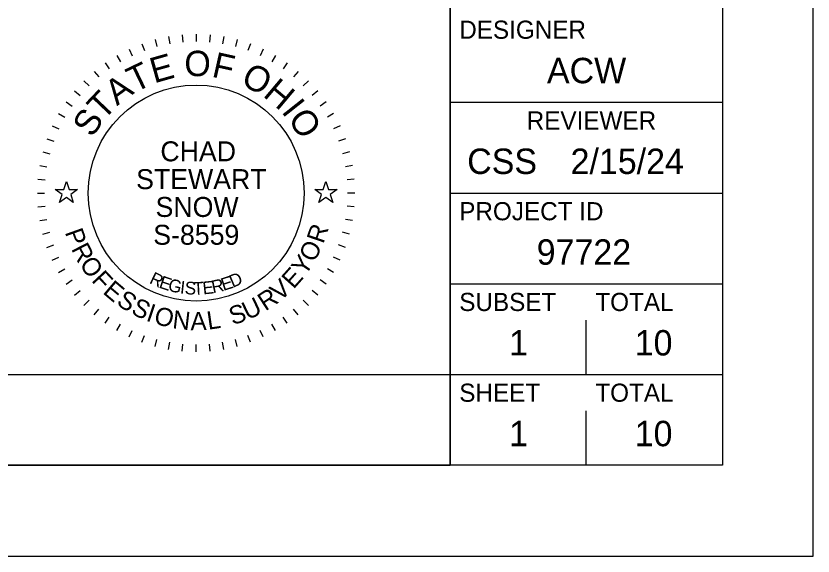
# Model space of a CAD drawing. Extents: x 0 to 59.1, y -2.4 to 22.
# Drawn here: x 29.607 to 34, y 0 to 2.976 of the extents above; entities that cross this region are included whole.
import ezdxf

# ---------------------------------------------------------------- set-up
doc = ezdxf.new("R2010")
doc.units = 0
for name, color, linetype in [('Default', 7, 'Continuous'), ('SH_Border', 7, 'Continuous'), ('SH_Cut_Line', 7, 'Continuous'), ('SH_Data', 7, 'Continuous')]:
    doc.layers.add(name, color=color, linetype=linetype)

msp = doc.modelspace()

# ---------------------------------------------------------------- linework, layer by layer
at = {"layer": 'Default'}
for points in [[(29.8236, 2.02), (29.8705, 2.02), (29.885, 2.0645), (29.8995, 2.02), (29.9464, 2.02), (29.9085, 1.9924), (29.923, 1.9478), (29.885, 1.9754), (29.847, 1.9478), (29.8615, 1.9924)], [(31.2536, 2.02), (31.3005, 2.02), (31.315, 2.0645), (31.3295, 2.02), (31.3764, 2.02), (31.3385, 1.9924), (31.353, 1.9478), (31.315, 1.9754), (31.277, 1.9478), (31.2915, 1.9924)]]:
    msp.add_lwpolyline(points, close=True, dxfattribs=at)
at = {"layer": 'SH_Border'}
for p, q in [((32, 0.5), (32, 21.5)), ((32, 2.5), (33.5, 2.5)), ((32, 2), (33.5, 2)), ((32, 1.5), (33.5, 1.5)), ((32, 1), (33.5, 1))]:
    msp.add_line(p, q, dxfattribs=at)
msp.add_lwpolyline([(1.5, 21.5), (33.5, 21.5), (33.5, 0.5), (1.5, 0.5)], close=True, dxfattribs=at)
at = {"layer": 'SH_Cut_Line'}
msp.add_lwpolyline([(0, 0), (34, 0), (34, 22), (0, 22)], close=True, dxfattribs=at)
at = {"layer": 'SH_Data'}
for p, q in [((32, 3.75), (32, 0.5)), ((30.4481, 2.8617), (30.455, 2.8223)), ((30.5237, 2.8717), (30.5272, 2.8318)), ((30.6, 2.875), (30.6, 2.835)), ((30.6763, 2.8717), (30.6728, 2.8318)), ((30.7519, 2.8617), (30.745, 2.8223)), ((30.3007, 2.8222), (30.3144, 2.7846)), ((30.3735, 2.8452), (30.3839, 2.8065)), ((30.8265, 2.8452), (30.8161, 2.8065)), ((30.8993, 2.8222), (30.8856, 2.7846)), ((30.2302, 2.793), (30.2471, 2.7568)), ((30.9698, 2.793), (30.9529, 2.7568)), ((30.1625, 2.7578), (30.1825, 2.7231)), ((31.0375, 2.7578), (31.0175, 2.7231)), ((30.0981, 2.7168), (30.1211, 2.684)), ((31.1019, 2.7168), (31.0789, 2.684)), ((30.0376, 2.6703), (30.0633, 2.6396)), ((31.1624, 2.6703), (31.1367, 2.6396)), ((29.9813, 2.6187), (30.0096, 2.5904)), ((31.2187, 2.6187), (31.1904, 2.5904)), ((29.9297, 2.5624), (29.9604, 2.5367)), ((31.2703, 2.5624), (31.2396, 2.5367)), ((29.8832, 2.5019), (29.916, 2.4789)), ((31.3168, 2.5019), (31.284, 2.4789)), ((29.8422, 2.4375), (29.8769, 2.4175)), ((31.3578, 2.4375), (31.3231, 2.4175)), ((29.807, 2.3698), (29.8432, 2.3529)), ((31.393, 2.3698), (31.3568, 2.3529)), ((29.7778, 2.2993), (29.8154, 2.2856)), ((31.4222, 2.2993), (31.3846, 2.2856)), ((29.7548, 2.2265), (29.7935, 2.2161)), ((31.4452, 2.2265), (31.4065, 2.2161)), ((29.7383, 2.1519), (29.7777, 2.145)), ((31.4617, 2.1519), (31.4223, 2.145)), ((29.7283, 2.0763), (29.7682, 2.0728)), ((31.4717, 2.0763), (31.4318, 2.0728)), ((29.725, 2), (29.765, 2)), ((31.475, 2), (31.435, 2)), ((29.7283, 1.9237), (29.7682, 1.9272)), ((31.4717, 1.9237), (31.4318, 1.9272)), ((29.7383, 1.8481), (29.7777, 1.855)), ((31.4617, 1.8481), (31.4223, 1.855)), ((29.7548, 1.7735), (29.7935, 1.7839)), ((31.4452, 1.7735), (31.4065, 1.7839)), ((29.7778, 1.7007), (29.8154, 1.7144)), ((31.4222, 1.7007), (31.3846, 1.7144)), ((29.807, 1.6302), (29.8432, 1.6471)), ((31.393, 1.6302), (31.3568, 1.6471)), ((29.8422, 1.5625), (29.8769, 1.5825)), ((31.3578, 1.5625), (31.3231, 1.5825)), ((29.8832, 1.4981), (29.916, 1.5211)), ((31.3168, 1.4981), (31.284, 1.5211)), ((29.9297, 1.4376), (29.9604, 1.4633)), ((31.2703, 1.4376), (31.2396, 1.4633)), ((29.9813, 1.3813), (30.0096, 1.4096)), ((31.2187, 1.3813), (31.1904, 1.4096)), ((30.0376, 1.3297), (30.0633, 1.3604)), ((31.1624, 1.3297), (31.1367, 1.3604)), ((30.0981, 1.2832), (30.1211, 1.316)), ((30.1625, 1.2422), (30.1825, 1.2769)), ((31.0375, 1.2422), (31.0175, 1.2769)), ((31.1019, 1.2832), (31.0789, 1.316)), ((32.75, 1), (32.75, 1.3)), ((30.2302, 1.207), (30.2471, 1.2432)), ((30.9698, 1.207), (30.9529, 1.2432)), ((30.3007, 1.1778), (30.3144, 1.2154)), ((30.3735, 1.1548), (30.3839, 1.1935)), ((30.8265, 1.1548), (30.8161, 1.1935)), ((30.8993, 1.1778), (30.8856, 1.2154)), ((30.4481, 1.1383), (30.455, 1.1777)), ((30.5237, 1.1283), (30.5272, 1.1682)), ((30.6, 1.125), (30.6, 1.165)), ((30.6763, 1.1283), (30.6728, 1.1682)), ((30.7519, 1.1383), (30.745, 1.1777)), ((32.75, 0.5), (32.75, 0.8)), ((29.2, 0.5), (32, 0.5))]:
    msp.add_line(p, q, dxfattribs=at)
msp.add_lwpolyline([(29.2, 0.5), (29.2, 1), (32, 1), (32, 0.5)], close=True, dxfattribs=at)
msp.add_circle((30.6, 2), 0.595, dxfattribs=at)

# ---------------------------------------------------------------- texts
for s, height, p in [('DESIGNER', 0.1, (32.05, 2.85)), ('ACW', 0.14, (32.5334, 2.605)), ('REVIEWER', 0.1, (32.4218, 2.35)), ('CHAD', 0.11, (30.4029, 2.1749)), ('CSS', 0.14, (32.0938, 2.105)), ('2/15/24', 0.14, (32.6636, 2.105)), ('STEWART', 0.11, (30.2691, 2.0216)), ('SNOW', 0.11, (30.3763, 1.8684)), ('PROJECT ID', 0.1, (32.05, 1.85)), ('S-8559', 0.11, (30.3636, 1.7151)), ('97722', 0.14, (32.4768, 1.605)), ('SUBSET', 0.1, (32.05, 1.35)), ('TOTAL', 0.1, (32.8, 1.35)), ('1', 0.14, (32.3251, 1.105)), ('10', 0.14, (33.0171, 1.105)), ('SHEET', 0.1, (32.05, 0.85)), ('TOTAL', 0.1, (32.8, 0.85)), ('10', 0.14, (33.0171, 0.605)), ('1', 0.14, (32.3251, 0.605))]:
    msp.add_text(s, height=height, dxfattribs=at).set_placement(p)
for s, height, rotation, p in [('E', 0.14, 15.7571, (30.3684, 2.6038)), ('O', 0.14, 359.7812, (30.5347, 2.6443)), ('F', 0.14, 347.4362, (30.6811, 2.6417)), ('T', 0.14, 25.7167, (30.2616, 2.5518)), ('O', 0.14, 332.2586, (30.8398, 2.6015)), ('A', 0.14, 36.4747, (30.1634, 2.4781)), ('H', 0.14, 319.9136, (30.9632, 2.5361)), ('T', 0.14, 46.4344, (30.0883, 2.3964)), ('I', 0.14, 308.367, (31.0665, 2.4483)), ('S', 0.14, 57.1924, (30.0281, 2.3014)), ('O', 0.14, 303.1491, (31.1021, 2.4089)), ('P', 0.1, 289.7431, (29.8753, 1.7841)), ('R', 0.1, 70.983, (31.3009, 1.7167)), ('R', 0.1, 296.9802, (29.9093, 1.6927)), ('O', 0.1, 62.7428, (31.2501, 1.6133)), ('O', 0.1, 304.7158, (29.9532, 1.6079)), ('Y', 0.1, 55.5058, (31.2, 1.54)), ('E', 0.1, 48.2687, (31.1366, 1.4673)), ('F', 0.1, 312.956, (30.0192, 1.5158)), ('R', 0.07, 334.487, (30.3375, 1.5051)), ('E', 0.07, 341.04, (30.3906, 1.4801)), ('E', 0.07, 17.6836, (30.7498, 1.4602)), ('D', 0.07, 23.3052, (30.801, 1.477)), ('E', 0.1, 319.6885, (30.0808, 1.4504)), ('G', 0.07, 347.4752, (30.4414, 1.4618)), ('I', 0.07, 353.7858, (30.5091, 1.4468)), ('S', 0.07, 356.8926, (30.5358, 1.4429)), ('T', 0.07, 3.0061, (30.5857, 1.4387)), ('E', 0.07, 6.0117, (30.6389, 1.4412)), ('R', 0.07, 11.9184, (30.6925, 1.4474)), ('V', 0.1, 41.0316, (31.0615, 1.4007)), ('S', 0.1, 326.9255, (30.1554, 1.3885)), ('R', 0.1, 33.296, (30.9815, 1.3473)), ('S', 0.1, 334.1626, (30.236, 1.3374)), ('U', 0.1, 25.5604, (30.8833, 1.2986)), ('I', 0.1, 341.3997, (30.3191, 1.2979)), ('O', 0.1, 345.1351, (30.3618, 1.2821)), ('S', 0.1, 18.3234, (30.8005, 1.2711)), ('N', 0.1, 353.3752, (30.466, 1.2555)), ('A', 0.1, 1.1108, (30.5692, 1.2443)), ('L', 0.1, 8.3479, (30.6664, 1.2467))]:
    msp.add_text(s, height=height, rotation=rotation, dxfattribs=at).set_placement(p)

doc.saveas('drawing.dxf')
